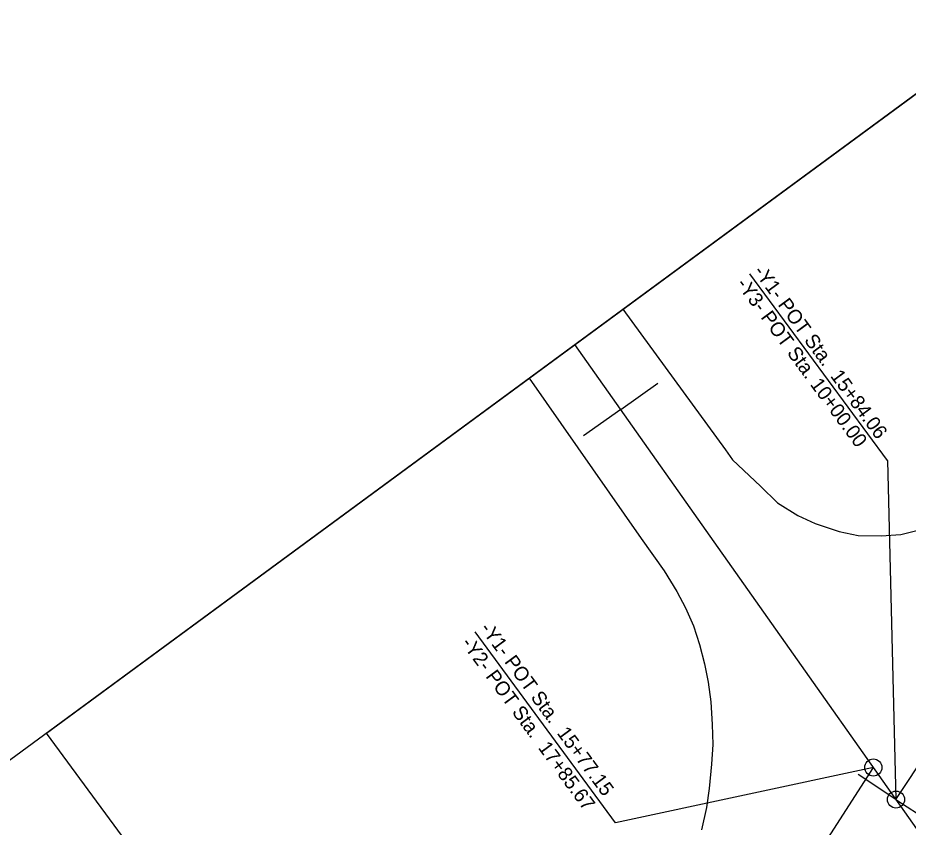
# Model space of a CAD drawing. Extents: x 1763480 to 1764420, y 711010 to 712012.
# Drawn here: x 1763698.2 to 1763855, y 711430.8 to 711573.4 of the extents above; entities that cross this region are included whole.
import ezdxf

# ---------------------------------------------------------------- set-up
doc = ezdxf.new("R2010")
doc.units = 0
for name, color, linetype in [('Old_Level_11', 7, 'Continuous'), ('Prop EOT', 7, 'Continuous'), ('Prop Horizontal Alignment Station Label', 7, 'Continuous'), ('Prop Horizontal Alignment Tick Large', 7, 'Continuous'), ('Prop Rem of Exist Asph Pvmt', 7, 'Continuous'), ('Sheet Block Revision CELL', 7, 'Continuous')]:
    doc.layers.add(name, color=color, linetype=linetype)

msp = doc.modelspace()

# ---------------------------------------------------------------- linework, layer by layer
at = {"layer": 'Old_Level_11'}
msp.add_lwpolyline([(1763871.46, 711571.1), (1763982.56, 711419.98), (1763814.35, 711296.3), (1763703.24, 711447.42)], close=True, dxfattribs=at)
msp.add_lwpolyline([(1763871.46, 711571.1), (1763982.56, 711419.98), (1763814.35, 711296.3), (1763703.24, 711447.42)], close=True, dxfattribs=at)
msp.add_lwpolyline([(1763871.46, 711571.1), (1763982.56, 711419.98), (1763814.35, 711296.3), (1763703.24, 711447.42)], close=True, dxfattribs=at)
msp.add_lwpolyline([(1763871.46, 711571.1), (1763982.56, 711419.98), (1763814.35, 711296.3), (1763703.24, 711447.42)], close=True, dxfattribs=at)
at = {"layer": 'Prop EOT'}
for p, q in [((1763804.76, 711522.06), (1763822.8, 711497.28)), ((1763788.26, 711509.93), (1763807.94, 711481.67)), ((1763822.8, 711497.28), (1763824.06, 711495.52)), ((1763824.06, 711495.52), (1763828.96, 711490.87)), ((1763828.96, 711490.87), (1763831.97, 711487.98)), ((1763831.97, 711487.98), (1763835.56, 711485.73)), ((1763835.56, 711485.73), (1763838.61, 711484.32)), ((1763838.61, 711484.32), (1763842.81, 711482.91)), ((1763853.71, 711482.36), (1763857.91, 711483.43)), ((1763807.94, 711481.67), (1763812, 711475.99)), ((1763842.81, 711482.91), (1763846.15, 711482.22)), ((1763846.15, 711482.22), (1763850.23, 711482.14)), ((1763850.23, 711482.14), (1763853.71, 711482.36)), ((1763812, 711475.99), (1763814.25, 711472.37)), ((1763814.25, 711472.37), (1763815.79, 711469.46)), ((1763815.79, 711469.46), (1763817.17, 711466.3)), ((1763817.17, 711466.3), (1763818.24, 711463.03)), ((1763818.24, 711463.03), (1763819.11, 711459.59)), ((1763819.11, 711459.59), (1763819.77, 711456.39)), ((1763819.77, 711456.39), (1763820.22, 711452.92)), ((1763820.22, 711452.92), (1763820.49, 711448.91)), ((1763820.49, 711448.91), (1763820.59, 711445.43)), ((1763820.59, 711445.43), (1763820.35, 711441.97)), ((1763820.35, 711441.97), (1763819.96, 711437.65)), ((1763819.96, 711437.65), (1763819.48, 711434.3)), ((1763819.48, 711434.3), (1763818.62, 711430.36))]:
    msp.add_line(p, q, dxfattribs=at)
at = {"layer": 'Prop Horizontal Alignment Station Label'}
msp.add_lwpolyline([(1763957.77, 711941.04), (1764052.94, 711811.6), (1764008.24, 711778.74), (1764295.85, 711387.56), (1764241.65, 711347.71), (1764301.88, 711263.14), (1763979.82, 711026.35), (1763792.92, 711280.55), (1763982.56, 711419.98), (1763871.46, 711571.1), (1763681.82, 711431.66), (1763535.55, 711630.61)], close=True, dxfattribs=at)
at = {"layer": 'Prop Horizontal Alignment Tick Large'}
for p, q in [((1763804.36, 711504.4), (1763810.9, 711509.01)), ((1763804.36, 711504.4), (1763797.82, 711499.78)), ((1763852.84, 711435.72), (1763846.15, 711440.11)), ((1763852.84, 711435.72), (1763859.53, 711431.33))]:
    msp.add_line(p, q, dxfattribs=at)
at = {"layer": 'Prop Rem of Exist Asph Pvmt'}
for p, q in [((1763851.32, 711495.41), (1763827.13, 711528.31)), ((1763851.32, 711495.41), (1763852.84, 711435.72)), ((1763803.46, 711431.62), (1763778.74, 711465.24)), ((1763848.85, 711441.36), (1763803.46, 711431.62))]:
    msp.add_line(p, q, dxfattribs=at)
for centre in [(1763848.85, 711441.36), (1763852.84, 711435.72)]:
    msp.add_circle(centre, 1.5, dxfattribs=at)
at = {"layer": 'Sheet Block Revision CELL'}
for p, q in [((1763852.84, 711435.72), (1763908.53, 711520.67)), ((1763904.48, 711362.57), (1763796.29, 711515.83)), ((1763783.03, 711338.91), (1763848.85, 711441.36))]:
    msp.add_line(p, q, dxfattribs=at)

# ---------------------------------------------------------------- texts
at = {"layer": 'Prop Rem of Exist Asph Pvmt'}
for s, p in [('-Y1- POT Sta.  15+84.06', (1763827.65, 711528.69)), ('-Y3- POT Sta. 10+00.00', (1763824.63, 711526.47)), ('-Y1- POT Sta.  15+77.15', (1763779.5, 711465.82)), ('-Y2- POT Sta.  17+85.67', (1763776.19, 711463.23))]:
    msp.add_text(s, height=2.5, rotation=306.325, dxfattribs=at).set_placement(p)

doc.saveas('drawing.dxf')
